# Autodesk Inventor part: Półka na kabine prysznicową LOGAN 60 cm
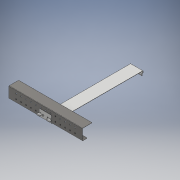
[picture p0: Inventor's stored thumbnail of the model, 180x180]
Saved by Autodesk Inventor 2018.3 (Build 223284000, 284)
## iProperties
Created: 2021-05
Part Number: Półka na kabine prysznicową LOGAN 60 cm
Material: Ogólny
Document SubType Name: Modeling
Designer: Verical
Density: 1 g/cm^3
Appearance: Domyślna
Author: Verical
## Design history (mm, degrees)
derived "Półka na kabine prysznicową LOGAN.iam"
node "Bryła1"
node "Uchwyt na Docie.ipt:1"
node "Odbojnik.ipt:1"
node "Odbojnik.ipt:2"
node "Półka prysznicowa - 60 cm.ipt:1"
node "Śruba motylkowa.ipt:3"
node "Śruba motylkowa.ipt:4"
node "Śruba imbusowa.ipt:3"
node "Śruba imbusowa.ipt:4"
node "Odbojnik większy.ipt:1"
node "Odbojnik większy.ipt:2"
